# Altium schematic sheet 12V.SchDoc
size A4; SheetNumber: 1; SheetTotal: 1
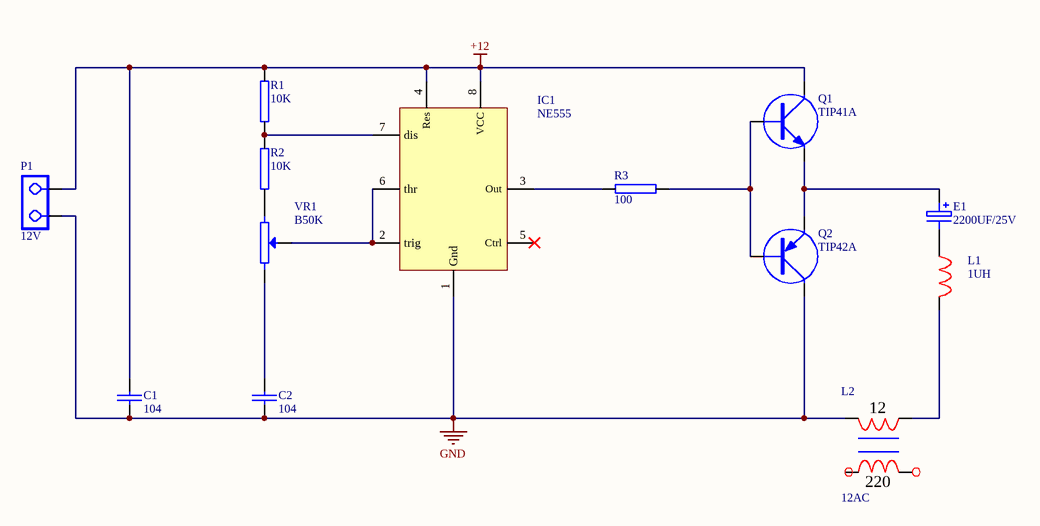
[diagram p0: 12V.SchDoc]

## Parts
C1  104  [C7.5]
C2  104  [C7.5]
E1  2200UF/25V  [E16]
IC1  NE555  [DIP8]
L1  1UH  [H8]
L2  12AC  [2P-3.96]
P1  12V  [2PIN]
Q1  TIP41A  [TO220]
Q2  TIP42A  [TO220]
R1  10K  [R]
R2  10K  [R]
R3  100  [R]
VR1  B50K  [VR1]

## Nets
+12: C1.1 IC1.4(Res) IC1.8(VCC) P1.2 Q1.C R1.2
GND: C1.2 C2.2 IC1.1(Gnd) L2.1(gnd) P1.1 Q2.c
NetC2_1: C2.1 VR1.2
NetE1_1: E1.1 Q1.E Q2.e
NetE1_2: E1.2 L1.1
NetIC1_2: IC1.2(trig) IC1.6(thr) VR1.w1
NetIC1_3: IC1.3(Out) R3.2
NetIC1_7: IC1.7(dis) R1.1 R2.2
NetL1_2: L1.2 L2.2(gnd)
NetQ1_B: Q1.B Q2.b R3.1
NetR2_1: R2.1 VR1.1

Not connected (* = marked no-connect by the designer): IC1 5(Ctrl)*

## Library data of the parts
C1 C2 = C
E1 = E
L1 = L
P1 = 2PIN
Q1 = NPN
Q2 = PNP
R1-R3 = R
VR1 = VR1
